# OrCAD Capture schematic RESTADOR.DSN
size A
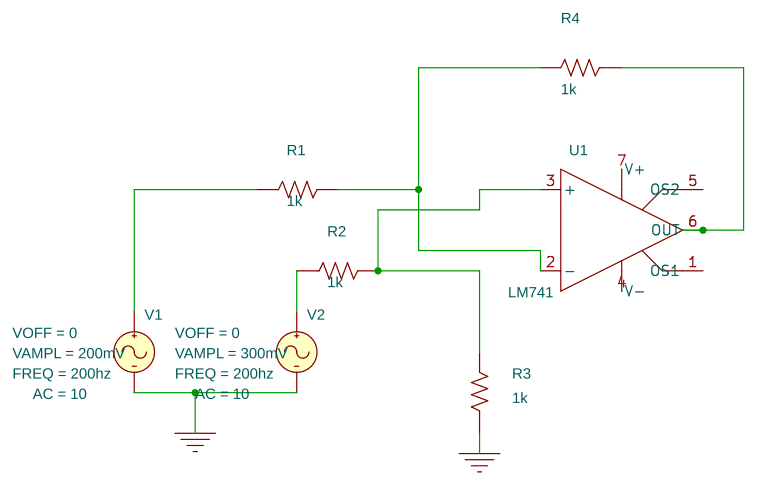
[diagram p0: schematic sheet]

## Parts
R1  1k  [AX/RC05]
R2  1k  [AX/RC05]
R3  1k  [AX/RC05]
R4  1k  [AX/RC05]
U1  LM741  [DIP.100/8/W.300/L.450]
V1  VSIN
V2  VSIN

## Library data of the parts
R1-R4 = r
U1 = LM741
V1 = VSIN: AC: 10; FREQ: 200hz; VAMPL: 200mV; VOFF: 0
V2 = VSIN: AC: 10; FREQ: 200hz; VAMPL: 300mV; VOFF: 0

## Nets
0: R3.1 V1.2(-) V2.2(-)
V+: U1.7(V+)
V-: U1.4(V-)
N00264: R2.1 V2.1(+)
N00268: R1.1 V1.1(+)
N00275: R1.2 R4.2 U1.2(-)
N00287: R2.2 R3.2 U1.3(+)
N00324: R4.1 U1.6(OUT)

Not connected (* = marked no-connect by the designer): U1 1(OS1) 5(OS2)
